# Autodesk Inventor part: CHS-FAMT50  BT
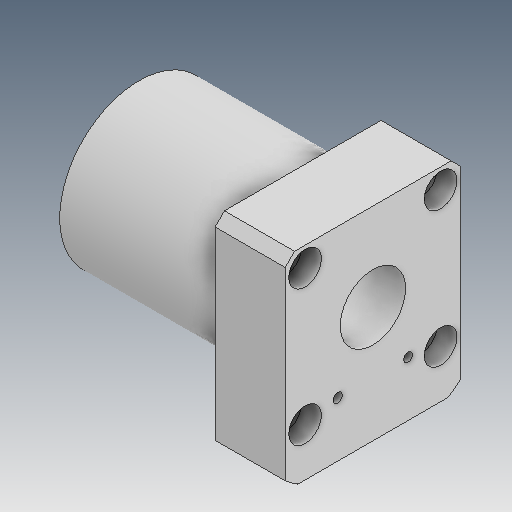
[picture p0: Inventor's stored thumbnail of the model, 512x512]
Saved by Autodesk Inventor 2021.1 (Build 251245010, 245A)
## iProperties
Created: 2019-04
Part Number: CHS-FAMT50  BT
Material: Ogólny
Document SubType Name: Modeling
Designer: user
Density: 1 g/cm^3
Appearance: Domyślna
Author: user
Revision Number: ÈÎºÎ
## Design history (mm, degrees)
feature "ÊäÈë1"
node "Bryła1"
